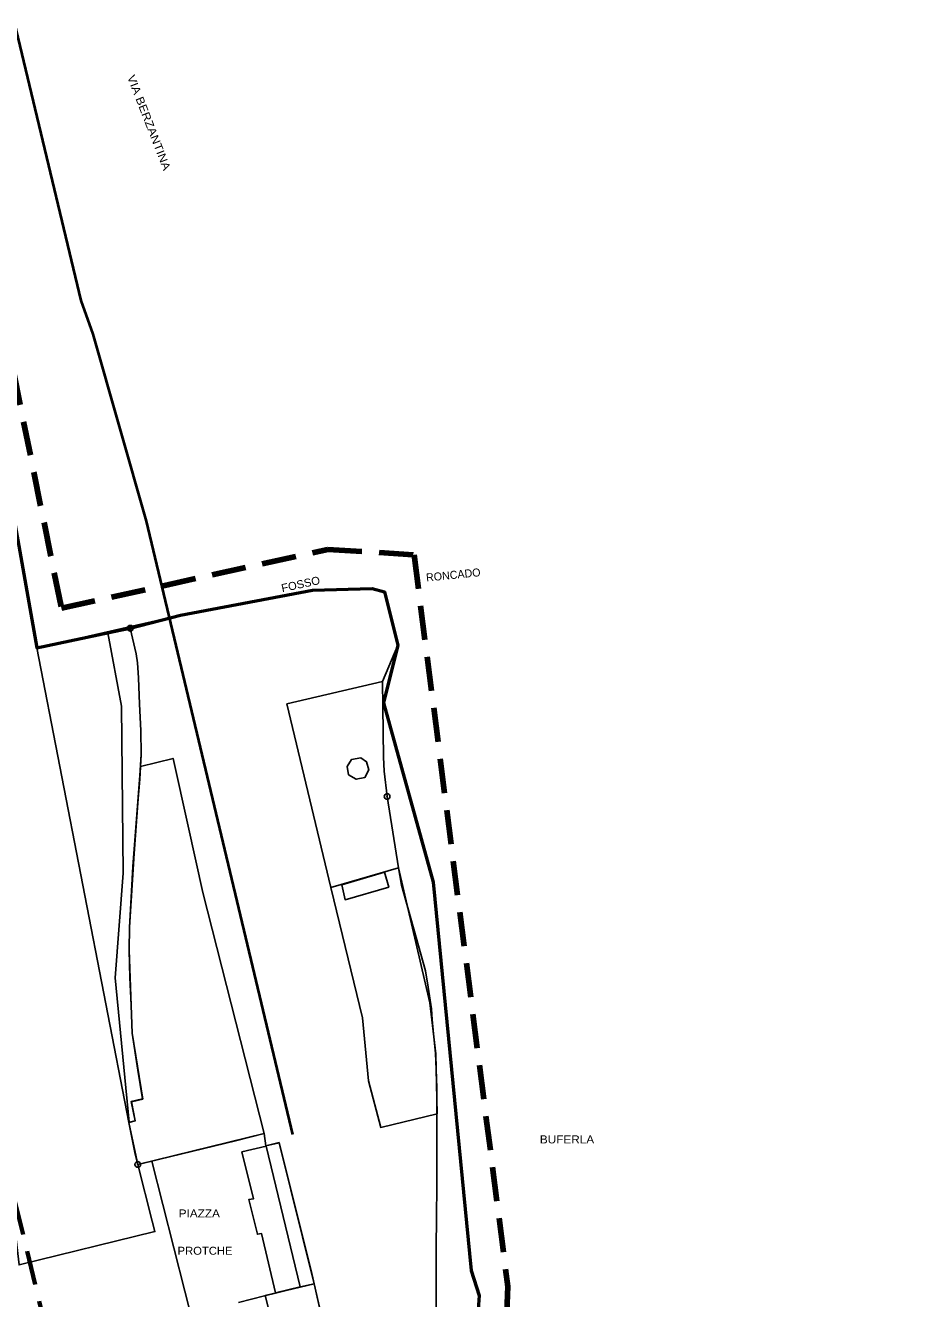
# Model space of a CAD drawing. Extents: x 654952 to 658955, y 890426 to 894481.
# Drawn here: x 658161.5 to 658467.8, y 891242 to 891687.4 of the extents above; entities that cross this region are included whole.
import ezdxf

# ---------------------------------------------------------------- set-up
doc = ezdxf.new("R2010")
doc.units = 0
doc.header["$LTSCALE"] = 4
doc.header["$PDMODE"] = 32
doc.header["$PDSIZE"] = 2
doc.linetypes.add('MEDIUM_DASHED', pattern=[4.5, 3, -1.5])
for name, color, linetype, lineweight in [('1', 7, 'Continuous', 25), ('18', 7, 'Continuous', 25), ('4', 7, 'Continuous', 25), ('43', 7, 'Continuous', 25), ('45', 7, 'Continuous', 25), ('55', 7, 'Continuous', 25), ('59', 7, 'Continuous', 53), ('7', 7, 'MEDIUM_DASHED', 100), ('9', 7, 'Continuous', 25)]:
    doc.layers.add(name, color=color, linetype=linetype, lineweight=lineweight)
doc.layers.add('58', color=7, linetype='Continuous')

msp = doc.modelspace()

# ---------------------------------------------------------------- linework, layer by layer
at = {"layer": '1'}
for points in [[(658205.89, 891269.14), (658206.8, 891265.48), (658159.27, 891253.81), (658132.26, 891484.14), (658144.06, 891484.59)], [(658236.11, 891240.63), (658245.2, 891242.97), (658249.04, 891243.93), (658257.71, 891246.09), (658262.54, 891247.12), (658250.31, 891296.5), (658245.59, 891295.44), (658244.99, 891299.72), (658200.81, 891288.96), (658205.89, 891269.14)]]:
    msp.add_lwpolyline(points, dxfattribs=at)
for points in [[(658274.54, 891425.27), (658274.04, 891428.14), (658275.57, 891430.57), (658278.82, 891431.18), (658280.89, 891429.86), (658281.63, 891427.03), (658280.3, 891424.38), (658277.25, 891423.71)], [(658272.23, 891386.78), (658287.2, 891391.16), (658288.64, 891385.99), (658273.37, 891381.58)]]:
    msp.add_lwpolyline(points, close=True, dxfattribs=at)
at = {"layer": '18'}
for points in [[(658288.04, 891417.69), (658287.07, 891426.56), (658286.77, 891431.44), (658286.48, 891457.94), (658252.99, 891450.05), (658268.41, 891385.81), (658292.07, 891392.72)], [(658235.06, 891297.22), (658244.99, 891299.72), (658223.52, 891384.04), (658218.45, 891407.26), (658213.18, 891430.98), (658201.8, 891428.16), (658199.5, 891397.72), (658197.88, 891371.98), (658197.74, 891363.86), (658198.84, 891334.88), (658202.57, 891311.82), (658198.61, 891310.89), (658199.89, 891304.2), (658197.7, 891303.67), (658200.81, 891288.95)]]:
    msp.add_lwpolyline(points, close=True, dxfattribs=at)
msp.add_point((658288.04, 891417.69), dxfattribs=at)
at = {"layer": '4'}
msp.add_line((658262.5, 891247.22), (658245.36, 891243.07), dxfattribs=at)
msp.add_lwpolyline([(658237.21, 891293.3), (658241.26, 891276.9), (658239.7, 891276.72), (658242.65, 891264.52), (658244.15, 891264.78), (658249.02, 891243.98), (658257.69, 891246.16), (658245.7, 891295.34)], close=True, dxfattribs=at)
msp.add_lwpolyline([(658245.36, 891243.07), (658249.11, 891228.29), (658240.77, 891226.17), (658243.51, 891214.08), (658247.24, 891215.06), (658248.07, 891212.05), (658252.92, 891213.24), (658253.09, 891212.58), (658269.5, 891216.54), (658262.5, 891247.22)], dxfattribs=at)
at = {"layer": '43'}
for points in [[(658198.2, 891476.54), (658194.36, 891475.84), (658190.27, 891474.97)], [(658190.27, 891474.97), (658195.12, 891449.31), (658195.65, 891390.86)], [(658195.65, 891390.86), (658192.95, 891354.26), (658197.78, 891303.69), (658199.89, 891304.2), (658198.5, 891311), (658202.46, 891311.93), (658198.84, 891334.88), (658198.45, 891344.64), (658198.06, 891354.41), (658197.74, 891363.86), (658197.88, 891371.98), (658198.56, 891384.56), (658199.09, 891393.19), (658199.98, 891405.37), (658200.56, 891412.91), (658201.57, 891425.05), (658201.99, 891432.42), (658201.83, 891440.75), (658201.42, 891449.95), (658201.01, 891459.15), (658200.74, 891464.46), (658200.22, 891467.65), (658198.2, 891476.54)]]:
    msp.add_lwpolyline(points, dxfattribs=at)
msp.add_point((658198.2, 891476.54), dxfattribs=at)
at = {"layer": '45', "lineweight": 40}
msp.add_lwpolyline([(658255.04, 891299.42), (658203.84, 891513.99), (658185.17, 891579.38), (658180.96, 891591.18), (658163.61, 891663.81), (658152.28, 891710.65), (658130.52, 891805.34), (658124.86, 891837.86), (658117.94, 891891.31), (658114.27, 891937.11), (658113.14, 891975.89), (658114.39, 892042.46), (658120.14, 892108.76), (658129.47, 892170.76), (658133.5, 892192.94), (658192.63, 892440.44)], dxfattribs=at)
at = {"layer": '45'}
for points in [[(658291.78, 891470.63), (658287.13, 891489.25), (658282.79, 891490.5), (658262, 891489.87), (658233.39, 891484.25), (658215.78, 891481.18), (658198.2, 891476.54), (658200.22, 891467.65), (658200.74, 891464.46), (658201.01, 891459.15), (658201.42, 891449.95), (658201.83, 891440.75), (658201.99, 891432.42), (658201.49, 891423.77), (658200.56, 891412.91), (658199.98, 891405.37), (658199.09, 891393.19), (658198.56, 891384.56), (658197.88, 891371.98), (658197.74, 891363.86), (658198.06, 891354.41), (658198.45, 891344.64), (658198.84, 891334.88), (658200.87, 891321.94), (658202.46, 891311.93), (658198.5, 891311), (658199.89, 891304.2), (658197.7, 891303.67), (658199.94, 891292.56), (658200.81, 891288.95), (658235.06, 891297.22), (658244.99, 891299.72), (658245.59, 891295.44), (658250.27, 891296.6), (658255.86, 891274.19), (658261.46, 891251.79), (658268.52, 891220.82)], [(658262, 891489.87), (658282.79, 891490.5), (658287.13, 891489.25), (658291.78, 891470.63), (658286.82, 891450.45), (658304.19, 891387.75), (658317.53, 891251.79), (658320.32, 891243.1)], [(658165.52, 891469.7), (658215.78, 891481.18), (658262, 891489.87)], [(658205.78, 891290.15), (658200.81, 891288.95), (658199.94, 891292.56), (658197.7, 891303.67), (658165.52, 891469.7)], [(658311.24, 891127), (658313.13, 891134.91), (658306.49, 891178.17), (658305.21, 891216.08), (658305.25, 891262.13), (658305.35, 891268.02), (658305.43, 891283.96), (658305.52, 891299.89), (658305.43, 891308.15), (658305.46, 891315.77), (658305.24, 891322.28), (658305.02, 891327.76), (658304.14, 891335.88), (658303.85, 891339.65), (658303.57, 891343.42), (658302.48, 891350.94), (658301.51, 891356.64), (658293.05, 891386.66), (658292.07, 891392.72), (658268.41, 891385.81), (658252.99, 891450.05), (658286.48, 891457.94), (658291.78, 891470.63)], [(658221.11, 891229.42), (658205.78, 891290.15)], [(658320.32, 891243.1), (658316.29, 891187.54)]]:
    msp.add_lwpolyline(points, dxfattribs=at)
at = {"layer": '45', "linetype": 'MEDIUM_DASHED', "lineweight": 70}
msp.add_lwpolyline([(658467.75, 890621.37), (658447.66, 890651.14), (658324.04, 890835.2), (658279.74, 890902.58), (658248.15, 890956.2), (658220.13, 891019.53), (658157.73, 891276.4)], dxfattribs=at)
at = {"layer": '55'}
for points in [[(658165.52, 891469.7), (658151.87, 891546.37), (658127.68, 891653.47), (658089.83, 891749.07), (658069.36, 891782.29), (658056.07, 891803.35), (658076.64, 891759.22), (658095.7, 891702.95), (658108.65, 891667.2), (658116.83, 891642.7), (658119.03, 891634.56), (658119.93, 891626.33), (658110.99, 891620.58)], [(658200.81, 891288.95), (658199.94, 891292.56), (658197.7, 891303.67), (658165.52, 891469.7)], [(658206.56, 891173.02), (658218.69, 891222.69), (658219.51, 891226.01), (658220.1, 891228.19), (658221.11, 891229.42), (658205.78, 891290.15), (658200.81, 891288.95)]]:
    msp.add_lwpolyline(points, dxfattribs=at)
msp.add_point((658200.81, 891288.95), dxfattribs=at)
at = {"layer": '59'}
msp.add_lwpolyline([(658151.87, 891546.37), (658165.52, 891469.7), (658194.68, 891475.9), (658198.2, 891476.54), (658215.78, 891481.18), (658262, 891489.87), (658282.79, 891490.49), (658287.13, 891489.25), (658291.78, 891470.63), (658286.82, 891450.45), (658304.19, 891387.75), (658317.53, 891251.79), (658320.32, 891243.1), (658316.29, 891187.54)], dxfattribs=at)
at = {"layer": '7'}
msp.add_lwpolyline([(658139.37, 891654.66), (658174.09, 891483.56), (658267.3, 891504.15), (658297.51, 891502.22), (658330.3, 891246.22), (658327.72, 891183.18)], dxfattribs=at)
at = {"layer": '9'}
msp.add_lwpolyline([(658268.41, 891385.81), (658279.44, 891340.22), (658281.57, 891318.21), (658285.83, 891301.92), (658305.55, 891306.67), (658305.13, 891327.65), (658303.05, 891345.44), (658292.07, 891392.72)], close=True, dxfattribs=at)

# ---------------------------------------------------------------- texts
at = {"layer": '58'}
for s, height, rotation, width, p in [('VIA BERZANTINA', 2.799, 291.193, 1.15, (658197.03, 891669.45)), ('FOSSO', 2.798, 12.251, 1.05, (658251.37, 891489.15))]:
    msp.add_text(s, height=height, rotation=rotation, dxfattribs=dict(at, width=width)).set_placement(p)
msp.add_text('RONCADO', height=2.799, rotation=5.766, dxfattribs=at).set_placement((658301.84, 891492.87))
for s, width, p in [('BUFERLA', 1.1, (658341.52, 891296.31)), ('PIAZZA', 1.1, (658215.13, 891270.41)), ('PROTCHE', 1.05, (658214.73, 891257.35))]:
    msp.add_text(s, height=2.801, dxfattribs=dict(at, width=width)).set_placement(p)

doc.saveas('drawing.dxf')
